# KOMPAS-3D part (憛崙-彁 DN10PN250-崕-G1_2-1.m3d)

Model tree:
1. Объединить компоненты:1  (labels: СЕНС-ПР DN10PN250-НО-G1/2-1)

Referenced files in D:\Савин\!СЕНСОР\3D для заказчика\!Новый перечень\СЕНС-ПР\5. СЕНС-ПР-PN250-НО\DN10\: СЕНС-ПР DN10PN250-НО-G1_2-1.a3d
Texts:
  СЕНС-ПР DN10PN250-НО-G1/2-1
  ООО НПП Сенсор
